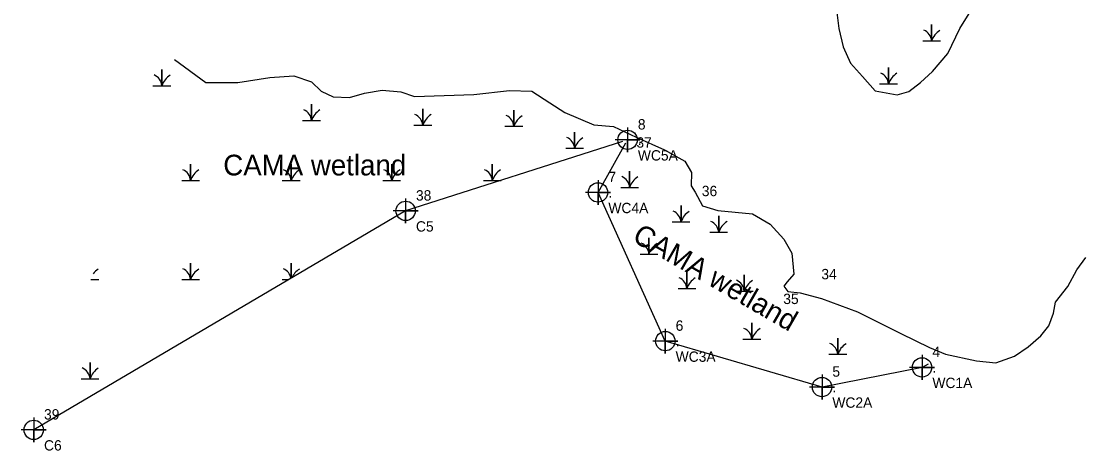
# Model space of a CAD drawing. Extents: x 2678633 to 2679425, y 623836 to 624637.
# Drawn here: x 2678632.5 to 2678889.8, y 624060.7 to 624164.5 of the extents above; entities that cross this region are included whole.
import ezdxf

# ---------------------------------------------------------------- set-up
doc = ezdxf.new("R2010")
doc.units = 0
for name, color, linetype in [('Exist Environmental Wetland Boundary', 7, 'Continuous'), ('Exist Environmental Wetland Boundary Cogo Comment', 7, 'Continuous'), ('Exist Environmental Wetland Boundary Cogo Elevation', 7, 'Continuous'), ('Exist Environmental Wetland Boundary Cogo Number', 7, 'Continuous'), ('Exist Environmental Wetland Boundary Cogo Point CELL', 7, 'Continuous'), ('Exist Environmental Wetland Boundary Text', 7, 'Continuous'), ('Exist Hydro Jurisdictional Stream or Body of Water NEU Mitigable', 7, 'Continuous'), ('Exist Hydro Swamp or Marsh', 7, 'Continuous')]:
    doc.layers.add(name, color=color, linetype=linetype)

msp = doc.modelspace()

# ---------------------------------------------------------------- linework, layer by layer
at = {"layer": 'Exist Environmental Wetland Boundary'}
for points in [[(2678777.86, 624135.44), (2678725.44, 624118.66), (2678635.53, 624065.75)], [(2678851.72, 624081.65), (2678850.28, 624080.85), (2678826.1, 624076.09), (2678788.22, 624087.19), (2678771.95, 624123.11), (2678778.67, 624135.1)]]:
    msp.add_lwpolyline(points, dxfattribs=at)
at = {"layer": 'Exist Environmental Wetland Boundary Cogo Point CELL'}
for points in [[(2678779.08, 624138.83), (2678779.08, 624132.83), (2678779.08, 624135.83), (2678782.08, 624135.83), (2678776.08, 624135.83)], [(2678771.95, 624126.11), (2678771.95, 624120.11), (2678771.95, 624123.11), (2678774.95, 624123.11), (2678768.95, 624123.11)], [(2678725.44, 624121.66), (2678725.44, 624115.66), (2678725.44, 624118.66), (2678728.44, 624118.66), (2678722.44, 624118.66)], [(2678788.22, 624090.19), (2678788.22, 624084.19), (2678788.22, 624087.19), (2678791.22, 624087.19), (2678785.22, 624087.19)], [(2678850.28, 624083.85), (2678850.28, 624077.85), (2678850.28, 624080.85), (2678853.28, 624080.85), (2678847.28, 624080.85)], [(2678826.1, 624079.09), (2678826.1, 624073.09), (2678826.1, 624076.09), (2678829.1, 624076.09), (2678823.1, 624076.09)], [(2678635.53, 624068.75), (2678635.53, 624062.75), (2678635.53, 624065.75), (2678638.53, 624065.75), (2678632.53, 624065.75)]]:
    msp.add_lwpolyline(points, dxfattribs=at)
for centre in [(2678779.08, 624135.83), (2678771.95, 624123.11), (2678725.44, 624118.66), (2678788.22, 624087.19), (2678850.28, 624080.85), (2678826.1, 624076.09), (2678635.53, 624065.75)]:
    msp.add_circle(centre, 2.34, dxfattribs=at)
at = {"layer": 'Exist Hydro Jurisdictional Stream or Body of Water NEU Mitigable'}
for points in [[(2678829.37, 624169.18), (2678830.15, 624162.74), (2678831.22, 624158.31), (2678833.01, 624154.39), (2678835.92, 624151.11), (2678838.94, 624147.69), (2678844.23, 624146.72), (2678847.12, 624147.52), (2678849.87, 624149.71), (2678852.82, 624152.33), (2678856.48, 624156.73), (2678859.43, 624162.76), (2678863.7, 624169.63)], [(2678669.6, 624155.25), (2678677.17, 624149.7), (2678684.87, 624149.7), (2678692.63, 624150.88), (2678698.4, 624151.28), (2678702.67, 624149.84), (2678704.99, 624147.62), (2678707.89, 624146.25), (2678711.91, 624146.06), (2678715.52, 624147.11), (2678719.74, 624147.85), (2678724.31, 624147.47), (2678727.62, 624146.34), (2678741.91, 624146.77), (2678750.59, 624147.74), (2678755.94, 624147.6), (2678760.31, 624144.75), (2678763.9, 624142.4), (2678770.9, 624139.44), (2678775.7, 624139.09), (2678781.16, 624136.46), (2678788.04, 624133.43), (2678792.97, 624130.67), (2678794.52, 624127.94), (2678794.44, 624124.72), (2678795.44, 624123.22), (2678797.17, 624119.89), (2678800.9, 624118.79), (2678809.27, 624117.98), (2678813.59, 624115.43), (2678816.83, 624111.79), (2678818.81, 624108.48), (2678819.32, 624103.37), (2678817.66, 624101.48), (2678816.83, 624100.46), (2678817.82, 624099.22), (2678820.81, 624098.85), (2678825.98, 624097.48), (2678834.65, 624094.25), (2678845.17, 624089.03), (2678852.1, 624085.68), (2678855.98, 624084.03), (2678863.48, 624082.39), (2678868.14, 624081.95), (2678872.6, 624083.54), (2678875.96, 624085.78), (2678878.98, 624088.5), (2678880.89, 624090.85), (2678882.09, 624093.97), (2678882.57, 624096.57), (2678885.49, 624100.38), (2678887.66, 624104.42), (2678889.84, 624107.37)]]:
    msp.add_lwpolyline(points, dxfattribs=at)
at = {"layer": 'Exist Hydro Swamp or Marsh'}
for p, q in [((2678852.6, 624161.5), (2678852.6, 624161.5)), ((2678666.52, 624150.69), (2678666.52, 624150.69)), ((2678702.69, 624142.27), (2678702.69, 624142.27)), ((2678729.58, 624141.14), (2678729.58, 624141.14)), ((2678751.61, 624140.88), (2678751.61, 624140.88)), ((2678766.29, 624135.56), (2678766.29, 624135.56)), ((2678779.58, 624126.12), (2678779.58, 624126.12)), ((2678792.01, 624117.77), (2678792.01, 624117.77)), ((2678801.13, 624115.3), (2678801.13, 624115.3)), ((2678784.27, 624110.03), (2678784.27, 624110.03)), ((2678793.44, 624101.67), (2678793.44, 624101.67)), ((2678807.29, 624101.06), (2678807.29, 624101.06)), ((2678809.13, 624089.45), (2678809.13, 624089.45)), ((2678829.91, 624085.78), (2678829.91, 624085.78))]:
    msp.add_line(p, q, dxfattribs=at)
for points in [[(2678850.45, 624159.72), (2678852.6, 624159.72), (2678852.6, 624163.66), (2678852.6, 624159.72), (2678854.75, 624159.72)], [(2678664.37, 624148.91), (2678666.52, 624148.91), (2678666.52, 624152.85), (2678666.52, 624148.91), (2678668.67, 624148.91)], [(2678840.03, 624149.35), (2678842.18, 624149.35), (2678842.18, 624153.3), (2678842.18, 624149.35), (2678844.33, 624149.35)], [(2678700.54, 624140.49), (2678702.69, 624140.49), (2678702.69, 624144.43), (2678702.69, 624140.49), (2678704.84, 624140.49)], [(2678727.43, 624139.36), (2678729.58, 624139.36), (2678729.58, 624143.31), (2678729.58, 624139.36), (2678731.74, 624139.36)], [(2678749.46, 624139.1), (2678751.61, 624139.1), (2678751.61, 624143.04), (2678751.61, 624139.1), (2678753.76, 624139.1)], [(2678764.14, 624133.78), (2678766.29, 624133.78), (2678766.29, 624137.72), (2678766.29, 624133.78), (2678768.44, 624133.78)], [(2678671.31, 624126.01), (2678673.46, 624126.01), (2678673.46, 624129.95), (2678673.46, 624126.01), (2678675.61, 624126.01)], [(2678695.62, 624126.01), (2678697.77, 624126.01), (2678697.77, 624129.95), (2678697.77, 624126.01), (2678699.92, 624126.01)], [(2678719.93, 624126.01), (2678722.08, 624126.01), (2678722.08, 624129.95), (2678722.08, 624126.01), (2678724.24, 624126.01)], [(2678744.25, 624126.01), (2678746.4, 624126.01), (2678746.4, 624129.95), (2678746.4, 624126.01), (2678748.55, 624126.01)], [(2678777.43, 624124.34), (2678779.58, 624124.34), (2678779.58, 624128.29), (2678779.58, 624124.34), (2678781.73, 624124.34)], [(2678789.86, 624115.99), (2678792.01, 624115.99), (2678792.01, 624119.93), (2678792.01, 624115.99), (2678794.16, 624115.99)], [(2678798.98, 624113.51), (2678801.13, 624113.51), (2678801.13, 624117.46), (2678801.13, 624113.51), (2678803.28, 624113.51)], [(2678782.12, 624108.24), (2678784.27, 624108.24), (2678784.27, 624112.19), (2678784.27, 624108.24), (2678786.42, 624108.24)], [(2678671.31, 624102.06), (2678673.46, 624102.06), (2678673.46, 624106), (2678673.46, 624102.06), (2678675.61, 624102.06)], [(2678697.77, 624102.38), (2678697.77, 624106), (2678697.77, 624102.38)], [(2678791.29, 624099.89), (2678793.44, 624099.89), (2678793.44, 624103.84), (2678793.44, 624099.89), (2678795.59, 624099.89)], [(2678805.14, 624099.28), (2678807.29, 624099.28), (2678807.29, 624103.22), (2678807.29, 624099.28), (2678809.44, 624099.28)], [(2678649.35, 624102.06), (2678651.3, 624102.06)], [(2678695.62, 624102.06), (2678697.22, 624102.06)], [(2678806.98, 624087.67), (2678809.13, 624087.67), (2678809.13, 624091.61), (2678809.13, 624087.67), (2678811.28, 624087.67)], [(2678827.76, 624084), (2678829.91, 624084), (2678829.91, 624087.94), (2678829.91, 624084), (2678832.06, 624084)], [(2678647, 624078.11), (2678649.15, 624078.11), (2678649.15, 624082.05), (2678649.15, 624078.11), (2678651.3, 624078.11)]]:
    msp.add_lwpolyline(points, dxfattribs=at)
for centre, radius, start, end in [((2678849.53, 624159.5), 3.07, 4.1403, 67.535), ((2678857.16, 624158.2), 4.81, 122.1274, 161.6222), ((2678663.45, 624148.68), 3.07, 4.1403, 67.535), ((2678671.08, 624147.39), 4.81, 122.1274, 161.6222), ((2678839.11, 624149.13), 3.07, 4.1403, 67.535), ((2678846.74, 624147.84), 4.81, 122.1274, 161.6222), ((2678699.62, 624140.27), 3.07, 4.1403, 67.535), ((2678707.25, 624138.97), 4.81, 122.1274, 161.6222), ((2678726.52, 624139.14), 3.07, 4.1403, 67.535), ((2678734.15, 624137.85), 4.81, 122.1274, 161.6222), ((2678748.55, 624138.87), 3.07, 4.1403, 67.535), ((2678756.17, 624137.58), 4.81, 122.1274, 161.6222), ((2678763.23, 624133.56), 3.07, 4.1403, 67.535), ((2678770.85, 624132.26), 4.81, 122.1274, 161.6222), ((2678670.39, 624125.78), 3.07, 4.1403, 67.535), ((2678678.02, 624124.49), 4.81, 122.1274, 161.6222), ((2678694.71, 624125.78), 3.07, 4.1403, 67.535), ((2678702.33, 624124.49), 4.81, 122.1274, 161.6222), ((2678719.02, 624125.78), 3.07, 4.1403, 67.535), ((2678726.65, 624124.49), 4.81, 122.1274, 161.6222), ((2678743.33, 624125.78), 3.07, 4.1403, 67.535), ((2678750.96, 624124.49), 4.81, 122.1274, 161.6222), ((2678776.52, 624124.12), 3.07, 4.1403, 67.535), ((2678784.14, 624122.83), 4.81, 122.1274, 161.6222), ((2678788.94, 624115.76), 3.07, 4.1403, 67.535), ((2678796.57, 624114.47), 4.81, 122.1274, 161.6222), ((2678798.07, 624113.29), 3.07, 4.1403, 67.535), ((2678805.7, 624112), 4.81, 122.1274, 161.6222), ((2678781.2, 624108.02), 3.07, 4.1403, 67.535), ((2678788.83, 624106.73), 4.81, 122.1274, 161.6222), ((2678653.71, 624100.54), 4.81, 122.1274, 142.7096), ((2678670.39, 624101.83), 3.07, 4.1403, 67.535), ((2678678.02, 624100.54), 4.81, 122.1274, 161.6222), ((2678694.71, 624101.83), 3.07, 9.8313, 67.535), ((2678702.33, 624100.54), 4.81, 122.1274, 156.2536), ((2678790.37, 624099.67), 3.07, 4.1403, 67.535), ((2678798, 624098.38), 4.81, 122.1274, 161.6222), ((2678804.23, 624099.06), 3.07, 4.1403, 67.535), ((2678811.85, 624097.76), 4.81, 122.1274, 161.6222), ((2678806.06, 624087.44), 3.07, 4.1403, 67.535), ((2678813.69, 624086.15), 4.81, 122.1274, 161.6222), ((2678826.84, 624083.78), 3.07, 4.1403, 67.535), ((2678834.47, 624082.48), 4.81, 122.1274, 161.6222), ((2678646.08, 624077.88), 3.07, 4.1403, 67.535), ((2678653.71, 624076.59), 4.81, 122.1274, 161.6222)]:
    msp.add_arc(centre, radius, start, end, dxfattribs=at)

# ---------------------------------------------------------------- texts
at = {"layer": 'Exist Environmental Wetland Boundary Cogo Comment'}
for s, p in [('WC5A', (2678781.58, 624130.83)), ('WC4A', (2678774.45, 624118.11)), ('C5', (2678727.94, 624113.66)), ('WC3A', (2678790.72, 624082.19)), ('WC1A', (2678852.78, 624075.85)), ('WC2A', (2678828.6, 624071.09)), ('C6', (2678638.03, 624060.75))]:
    msp.add_text(s, height=2.5, dxfattribs=at).set_placement(p)
at = {"layer": 'Exist Environmental Wetland Boundary Cogo Elevation'}
for p in [(2678781.58, 624134.58), (2678774.45, 624121.86), (2678790.72, 624085.94), (2678852.78, 624079.6), (2678828.6, 624074.84)]:
    msp.add_text('.', height=2.5, dxfattribs=at).set_placement(p)
at = {"layer": 'Exist Environmental Wetland Boundary Cogo Number'}
for s, p in [('8', (2678781.58, 624138.33)), ('37', (2678781.23, 624133.95)), ('7', (2678774.45, 624125.61)), ('38', (2678727.94, 624121.16)), ('36', (2678797.04, 624122.22)), ('34', (2678825.94, 624102.14)), ('35', (2678816.73, 624096.15)), ('6', (2678790.72, 624089.69)), ('4', (2678852.78, 624083.35)), ('5', (2678828.6, 624078.59)), ('39', (2678638.03, 624068.25))]:
    msp.add_text(s, height=2.5, dxfattribs=at).set_placement(p)
at = {"layer": 'Exist Environmental Wetland Boundary Text'}
msp.add_text('CAMA wetland', height=5, dxfattribs=at).set_placement((2678681.36, 624127.23))
msp.add_text('CAMA wetland', height=5, rotation=330, dxfattribs=at).set_placement((2678779.96, 624111.5))

doc.saveas('drawing.dxf')
